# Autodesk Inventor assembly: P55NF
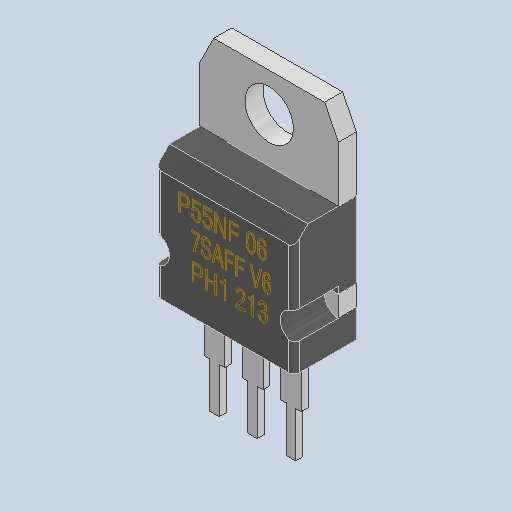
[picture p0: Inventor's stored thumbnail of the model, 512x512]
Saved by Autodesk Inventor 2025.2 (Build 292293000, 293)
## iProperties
Created: 2025-04
Part Number: P55NF
Description: PART--DESC
Document SubType Name: Assembly
Designer: BennF
Author: BennF
Revision Number: NONE
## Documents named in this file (4)
- C:\Users\BennF\Nextcloud\Benutzer\CNC JarBeRi\existing parts\Electronics\RepRap A4988 Shied (USE WITHOUT ARDUINO)\reprap-a4988-1.snapshot.1\RepRap\RepRap\P55NF.iam
- C:\Users\BennF\Nextcloud\Benutzer\CNC JarBeRi\existing parts\Electronics\RepRap A4988 Shied (USE WITHOUT ARDUINO)\reprap-a4988-1.snapshot.1\RepRap\RepRap\P55NF Geometry.ipt
- C:\Users\BennF\Nextcloud\Benutzer\CNC JarBeRi\existing parts\Electronics\RepRap A4988 Shied (USE WITHOUT ARDUINO)\reprap-a4988-1.snapshot.1\RepRap\RepRap\body2.ipt
- C:\Users\BennF\Nextcloud\Benutzer\CNC JarBeRi\existing parts\Electronics\RepRap A4988 Shied (USE WITHOUT ARDUINO)\reprap-a4988-1.snapshot.1\RepRap\RepRap\Name2.ipt
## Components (3 placed, 3 different names)
1. P55NF Geometry
2. body2
3. Name2
